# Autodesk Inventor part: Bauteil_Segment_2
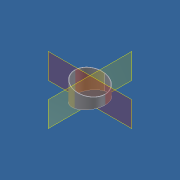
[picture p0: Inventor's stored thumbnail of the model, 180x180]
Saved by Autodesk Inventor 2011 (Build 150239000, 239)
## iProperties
Created: 2009-03
Part Number: Bauteil_Segment_2
Material: S235JR
Document SubType Name: Blech
Designer: Guido Walteich
Density: 7.86 g/cm^3
Flat Pattern Width: 49.112 cm
Flat Pattern Length: 9.54779 cm
Flat Pattern Area: 468.911 cm^2
Description: Blech
Mass: 738.822 g
Surface Area: 660.584 cm^2
Volume: 93.9977 cm^3
Sheet Metal Rule: Standard_mm
Stärke: 3 mm
d0: 160 mm
d6: 95 mm
Gestr_Neutral: 491 mm
Maße: = Ø<d0> x L=<d6> , aus Blech <Stärke> x <d6> x <Gestr_neutral>
Author: Guido Walteich
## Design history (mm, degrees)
node "Konturlasche1"
  sketch "Skizze2"
    geometry: L1 (-98, 0)-(98, 0) reference; L2 (0, -98.1)-(0, 98.6) reference; A1 r 80 centre (0, 0) between (-0.5, 79.998) and (0.5, 79.998); A2 r 0.5 centre (0, 80) between (0.5, 79.998) and (-0.5, 79.998)
    constraints: 5 point on circle, 2 centre point, 2 point on line, 1 midpoint
    dimensions: "d0" = 160 diameter of A1 (= Rohr_D); "d1" = 1 diameter of A2
workplane "Arbeitsebene1"
workplane "Arbeitsebene2"
sketch "Skizze6"
  geometry: L1 (80, 0)-(80, 95.478) reference; L2 (-80, 0)-(-80, 95.478) reference; L3 (-80, 95.478)-(80, 95.478) reference; L4 (80, 0)-(-80, 0) reference; L5 (-80, 31.826)-(80, 0); L6 (80, 95.478)-(-80, 63.652); 4 further points
  constraints: 4 end point, 2 point on line
  dimensions: "d21" = 11.25 deg angle of L5 L4 (= WINKEL); "d24" = 11.25 deg angle of L3 L6 (= WINKEL)
extrude "Extrusion2" cut sketch "Skizze6" stored distance "d25" = 320 (= 2 x Rohr_D); taper "d26" = 0 deg
node "Volumenkörper1"
feature "Grobblech1" dims "d2" = 3 (= BreiteBiegungsfreistellung), "d3" = 1.5 (= TiefeBiegungsfreistellung), "d4" = 6 (= MinimalRest), "d5" = 3 (= Biegeradius), "d6" = 95.47792 (= Länge_2), "d7" = 3 (= Biegeradius), "d8" = 3 (= Wandstärke), "d9" = 12 (= GrößeEckenfreistellung), "d10" = 3 (= Stärke), "d11" = 3 (= JacobiRadiusGröße), "Stärke" = 3 (= Wandstärke), "AbstandVerbindung" = 0.01
feature "Biegung1" dims "d2" = 3 (= BreiteBiegungsfreistellung), "d3" = 1.5 (= TiefeBiegungsfreistellung), "d4" = 6 (= MinimalRest), "d5" = 3 (= Biegeradius), "d7" = 3 (= Biegeradius), "d8" = 3 (= Wandstärke), "Stärke" = 3 (= Wandstärke), "AbstandVerbindung" = 0.01
feature "Ecke1" dims "d8" = 3 (= Wandstärke), "d9" = 12 (= GrößeEckenfreistellung), "d10" = 3 (= Stärke), "d11" = 3 (= JacobiRadiusGröße)
feature "Definition1"
other parameters: "KFaktor" = 4.4, "Biegeradius" = 3 (= Stärke), "BreiteBiegungsfreistellung" = 3 (= Stärke), "TiefeBiegungsfreistellung" = 1.5 (= 0.5 x Stärke), "GrößeEckenfreistellung" = 12 (= 4 x Stärke), "MinimalRest" = 6 (= 2 x Stärke), "Übergangsradius" = 3 (= Biegeradius), "JacobiRadiusGröße" = 3 (= Biegeradius), "Rohr_D" = 160 [user parameter; used in 3 equation terms], "WINKEL_1" = 1.9635 [user parameter], "WINKEL_2" = 1.9635 [user parameter], "Länge_2" = 95.47792 [user parameter; used in 1 equation term], "Wandstärke" = 3 [user parameter; used in 3 equation terms], "d12" = 0, "d13" = 0, "Gestr_Neutral" = 490.87375 (computed from Rohr_D, Wandstärke) [user parameter], "WINKEL" = 11.25 deg [user parameter; used in 2 equation terms], "Länge_1" = 47.73896 [user parameter], "Länge_3" = 95.47792 [user parameter], "Länge_4" = 95.47792 [user parameter], "Länge_5" = 47.73896 [user parameter], "ANZ_TEILE" = 39.78874 [user parameter], "GES_WINKEL" = 90 deg [user parameter], "Abstandsgröße" = 3 (= Stärke), "Gestr_Neutral" = 490.87375, "Länge_2" = 95.47792, "WINKEL_1" = 1.9635, "WINKEL_2" = 1.9635, "Wandstärke" = 3, "Biegeradius" = 3, "BreiteBiegungsfreistellung" = 3, "GrößeEckenfreistellung" = 12, "JacobiRadiusGröße" = 3, "MinimalRest" = 6, "Stärke" = 3, "TiefeBiegungsfreistellung" = 1.5, "Übergangsradius" = 3, "Länge_1" = 47.73896, "Länge_3" = 95.47792, "Länge_4" = 95.47792, "Länge_5" = 47.73896, "WINKEL" = 1.9635, "ANZ_TEILE" = 39.78874, "GES_WINKEL" = 90 deg, "Abstandsgröße" = 3
